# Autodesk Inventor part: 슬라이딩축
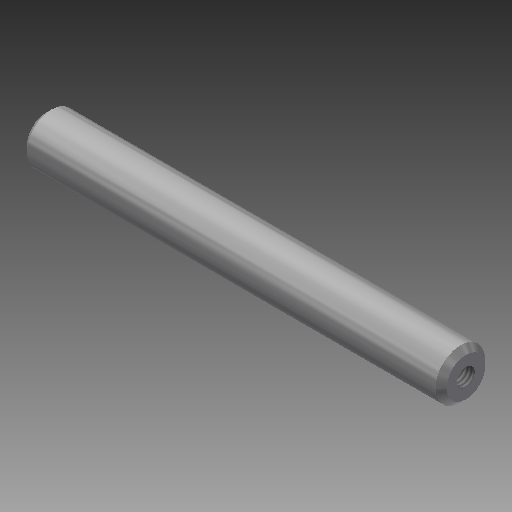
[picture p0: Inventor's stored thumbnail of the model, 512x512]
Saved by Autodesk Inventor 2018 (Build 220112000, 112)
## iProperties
Created: 2020-03
Part Number: 슬라이딩축
Material: 강철, 연강
Document SubType Name: Modeling
Designer: mduedu
Density: 7.86 g/cm^3
Appearance: 강철
Mass: 36.4568 g
Surface Area: 24.4681 cm^2
Volume: 4.63827 cm^3
Author: mduedu
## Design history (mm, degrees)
sketch "스케치1"
  geometry: C1 r 4.5 at (0, 0); 1 further point
  constraints: 1 centre point, 1 coincident
  dimensions: "d0" = 9 diameter of C1
extrude "돌출1" new body sketch "스케치1" stored distance "d1" = 76; taper "d2" = 0 deg
hole "구멍1" diameter "d5" = 3.242; stored, may be unused: countersink angle "d9" = 90 deg, drill point angle "d11" = 118 deg; dims "d3" = 10, "d4" = 10, "d6" = 8, "d7" = 4, "d8" = 2, "d10" = 10
chamfer "모따기1" distance "d12" = 1; stored, may be unused: second distance "d13" = 2, angle "d14" = 45 deg
node "솔리드1"
mirror "대칭1"
